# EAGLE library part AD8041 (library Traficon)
AD8041AR In Traficon stock en ook verkrijgbaar bij Farnell: AD8041ARZ, ordercode: 1311728 Drawer: CT
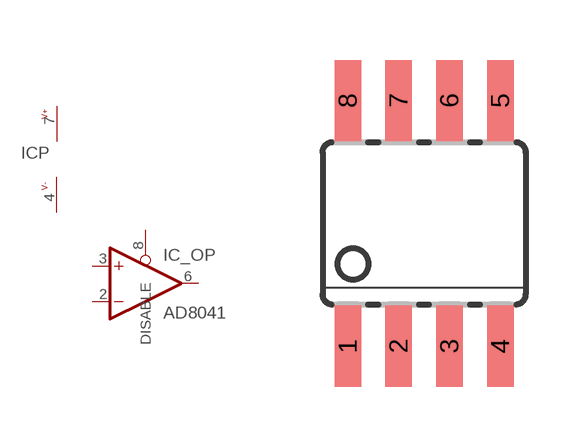
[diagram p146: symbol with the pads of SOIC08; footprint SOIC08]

Designator prefix IC; gates P=PWR+- _OP=OPAMP_DISABLE

## AD8041AR  [SOIC08]
2  _OP:-IN  in
3  _OP:+IN  in
4  P:V-  pas
6  _OP:OUT  out
7  P:V+  pas
8  _OP:DISABLE  in

## Footprint SOIC08 (pad centres in mm)
Small Outline Package
smd 0.66 x 2.032: 1 -1.905,-3.073; 2 -0.635,-3.073; 3 0.635,-3.073; 4 1.905,-3.073; 5 1.905,3.073; 6 0.635,3.073; 7 -0.635,3.073; 8 -1.905,3.073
